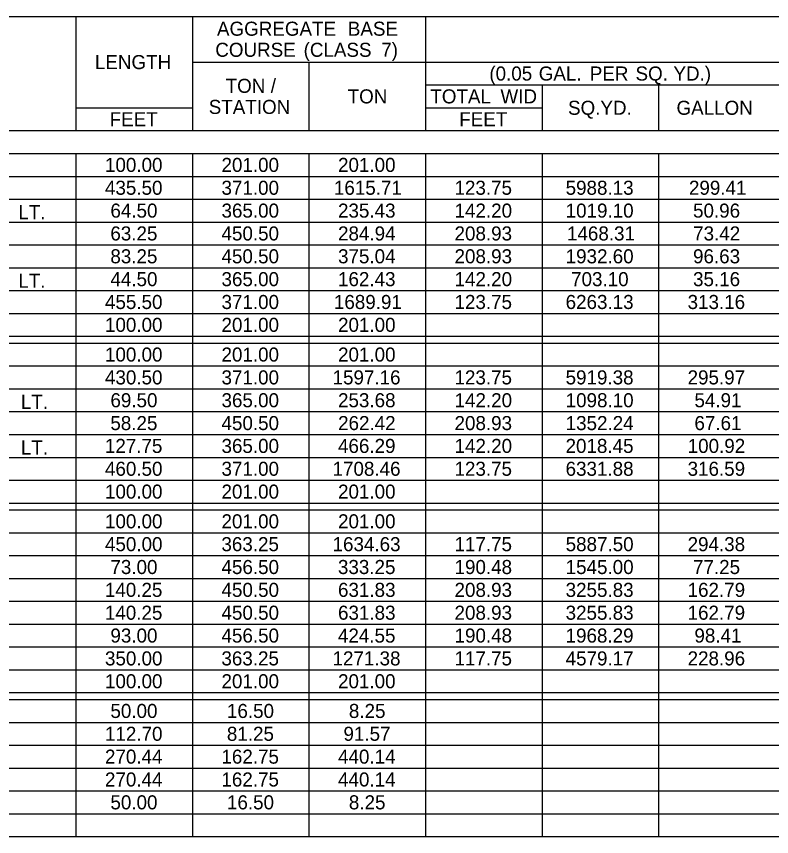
# Model space of a CAD drawing. Extents: x 977434 to 989596, y 1525697 to 1528336.
# Drawn here: x 982968.2 to 983226, y 1527821 to 1528101.1 of the extents above; entities that cross this region are included whole.
import ezdxf

# ---------------------------------------------------------------- set-up
doc = ezdxf.new("R2010")
doc.units = 0
doc.layers.add('Default', color=7, linetype='Continuous')

msp = doc.modelspace()

# ---------------------------------------------------------------- linework, layer by layer
at = {"layer": 'Default'}
for p, q in [((982704.74, 1528101.06), (984062.72, 1528101.06)), ((982988.66, 1528062.06), (982988.66, 1528101.06)), ((983028.44, 1528062.06), (983028.44, 1528101.06)), ((983108, 1528062.06), (983108, 1528101.06)), ((983028.44, 1528085.46), (984062.72, 1528085.46)), ((983068.22, 1528062.06), (983068.22, 1528085.46)), ((983108, 1528077.66), (983346.68, 1528077.66)), ((983147.78, 1528062.06), (983147.78, 1528077.66)), ((983187.56, 1528062.06), (983187.56, 1528077.66)), ((982988.66, 1528069.86), (983028.44, 1528069.86)), ((983028.44, 1528062.06), (983028.44, 1528069.86)), ((983108, 1528069.86), (983147.78, 1528069.86)), ((983147.78, 1528062.06), (983147.78, 1528069.86)), ((982704.74, 1528062.06), (984062.72, 1528062.06)), ((983028.44, 1528062.06), (983147.78, 1528062.06)), ((983147.78, 1528062.06), (983267.12, 1528062.06)), ((982704.74, 1528054.26), (984062.72, 1528054.26)), ((982988.66, 1527821.04), (982988.66, 1528054.26)), ((982988.66, 1527821.04), (982988.66, 1528054.26)), ((983028.44, 1527821.04), (983028.44, 1528054.26)), ((983028.44, 1527821.04), (983028.44, 1528054.26)), ((983068.22, 1527821.04), (983068.22, 1528054.26)), ((983068.22, 1527821.04), (983068.22, 1528054.26)), ((983108, 1527821.04), (983108, 1528054.26)), ((983108, 1527821.04), (983108, 1528054.26)), ((983147.78, 1527821.04), (983147.78, 1528054.26)), ((983147.78, 1527821.04), (983147.78, 1528054.26)), ((983187.56, 1527821.04), (983187.56, 1528054.26)), ((983187.56, 1527821.04), (983187.56, 1528054.26)), ((982704.74, 1528046.46), (984062.72, 1528046.46)), ((982704.74, 1528038.66), (984062.72, 1528038.66)), ((982704.74, 1528030.86), (984062.72, 1528030.86)), ((982704.74, 1528023.06), (984062.72, 1528023.06)), ((982704.74, 1528015.26), (984062.72, 1528015.26)), ((982704.74, 1528007.46), (984062.72, 1528007.46)), ((982704.74, 1527999.66), (984062.72, 1527999.66)), ((982704.74, 1527991.86), (984062.72, 1527991.86)), ((982704.74, 1527989.52), (984062.72, 1527989.52)), ((982704.74, 1527981.72), (984062.72, 1527981.72)), ((982704.74, 1527973.92), (984062.72, 1527973.92)), ((982704.74, 1527966.12), (984062.72, 1527966.12)), ((982704.74, 1527958.32), (984062.72, 1527958.32)), ((982704.74, 1527950.52), (984062.72, 1527950.52)), ((982704.74, 1527942.72), (984062.72, 1527942.72)), ((982704.74, 1527934.92), (984062.72, 1527934.92)), ((982704.74, 1527932.58), (984062.72, 1527932.58)), ((982704.74, 1527924.78), (984062.72, 1527924.78)), ((982704.74, 1527916.98), (984062.72, 1527916.98)), ((982704.74, 1527909.18), (984062.72, 1527909.18)), ((982704.74, 1527901.38), (984062.72, 1527901.38)), ((982704.74, 1527893.58), (984062.72, 1527893.58)), ((982704.74, 1527885.78), (984062.72, 1527885.78)), ((982704.74, 1527877.98), (984062.72, 1527877.98)), ((982704.74, 1527870.18), (984062.72, 1527870.18)), ((982704.74, 1527867.84), (984062.72, 1527867.84)), ((982704.74, 1527860.04), (984062.72, 1527860.04)), ((982704.74, 1527852.24), (984062.72, 1527852.24)), ((982704.74, 1527844.44), (984062.72, 1527844.44)), ((982704.74, 1527836.64), (984062.72, 1527836.64)), ((982704.74, 1527828.84), (984062.72, 1527828.84)), ((982704.74, 1527821.04), (983147.78, 1527821.04)), ((982704.74, 1527821.04), (984062.72, 1527821.04)), ((983147.78, 1527821.04), (983227.34, 1527821.04))]:
    msp.add_line(p, q, dxfattribs=at)

# ---------------------------------------------------------------- texts
for s, p in [('AGGREGATE', (983036.69, 1528094.46)), (' BASE', (983079.58, 1528094.46)), ('COURSE', (983036.12, 1528087.26)), (' (CLASS', (983064.48, 1528087.26)), (' 7)', (983090.98, 1528087.26)), ('LENGTH', (982995.02, 1528083.06)), ('(0.05', (983129.67, 1528079.16)), (' GAL.', (983144.75, 1528079.16)), (' PER', (983162.17, 1528079.16)), (' SQ.', (983177.79, 1528079.16)), (' YD.)', (983190.74, 1528079.16)), ('TON', (983039.65, 1528074.96)), (' /', (983053.27, 1528074.96)), ('TON', (983081.3, 1528071.36)), ('TOTAL', (983109.53, 1528071.36)), (' WID', (983131.68, 1528071.36)), ('STATION', (983033.88, 1528067.76)), ('SQ.YD.', (983156.53, 1528067.46)), ('GALLON', (983193.56, 1528067.46)), ('FEET', (983000.05, 1528063.56)), ('FEET', (983119.39, 1528063.56)), ('100.00', (982998.46, 1528047.96)), ('201.00', (983038.24, 1528047.96)), ('201.00', (983078.02, 1528047.96)), ('435.50', (982998.46, 1528040.16)), ('371.00', (983038.24, 1528040.16)), ('1615.71', (983076.61, 1528040.16)), ('123.75', (983117.77, 1528040.16)), ('5988.13', (983155.71, 1528040.16)), ('299.41', (983197.81, 1528040.16)), (' LT.', (982967.1, 1528031.82)), ('64.50', (983000.32, 1528032.36)), ('365.00', (983038.24, 1528032.36)), ('235.43', (983078.01, 1528032.36)), ('142.20', (983117.8, 1528032.36)), ('1019.10', (983155.72, 1528032.36)), ('50.96', (983199.21, 1528032.36)), ('63.25', (983000.3, 1528024.56)), ('450.50', (983038.24, 1528024.56)), ('284.94', (983078.02, 1528024.56)), ('208.93', (983117.79, 1528024.56)), ('1468.31', (983156.17, 1528024.56)), ('73.42', (983199.24, 1528024.56)), ('83.25', (983000.3, 1528016.76)), ('450.50', (983038.24, 1528016.76)), ('375.04', (983078.02, 1528016.76)), ('208.93', (983117.79, 1528016.76)), ('1932.60', (983155.72, 1528016.76)), ('96.63', (983199.21, 1528016.76)), (' LT.', (982967.1, 1528008.42)), ('44.50', (983000.32, 1528008.96)), ('365.00', (983038.24, 1528008.96)), ('162.43', (983078.01, 1528008.96)), ('142.20', (983117.8, 1528008.96)), ('703.10', (983157.58, 1528008.96)), ('35.16', (983199.21, 1528008.96)), ('455.50', (982998.46, 1528001.16)), ('371.00', (983038.24, 1528001.16)), ('1689.91', (983076.61, 1528001.16)), ('123.75', (983117.77, 1528001.16)), ('6263.13', (983155.71, 1528001.16)), ('313.16', (983197.35, 1528001.16)), ('100.00', (982998.46, 1527993.36)), ('201.00', (983038.24, 1527993.36)), ('201.00', (983078.02, 1527993.36)), ('100.00', (982998.46, 1527983.22)), ('201.00', (983038.24, 1527983.22)), ('201.00', (983078.02, 1527983.22)), ('430.50', (982998.46, 1527975.42)), ('371.00', (983038.24, 1527975.42)), ('1597.16', (983076.15, 1527975.42)), ('123.75', (983117.77, 1527975.42)), ('5919.38', (983155.7, 1527975.42)), ('295.97', (983197.35, 1527975.42)), (' LT.', (982967.97, 1527967.08)), ('69.50', (983000.32, 1527967.62)), ('365.00', (983038.24, 1527967.62)), ('253.68', (983078.01, 1527967.62)), ('142.20', (983117.8, 1527967.62)), ('1098.10', (983155.72, 1527967.62)), ('54.91', (983199.68, 1527967.62)), ('58.25', (983000.3, 1527959.82)), ('450.50', (983038.24, 1527959.82)), ('262.42', (983078.04, 1527959.82)), ('208.93', (983117.79, 1527959.82)), ('1352.24', (983155.72, 1527959.82)), ('67.61', (983199.68, 1527959.82)), (' LT.', (982967.97, 1527951.48)), ('127.75', (982998.43, 1527952.02)), ('365.00', (983038.24, 1527952.02)), ('466.29', (983078.01, 1527952.02)), ('142.20', (983117.8, 1527952.02)), ('2018.45', (983155.69, 1527952.02)), ('100.92', (983197.38, 1527952.02)), ('460.50', (982998.46, 1527944.22)), ('371.00', (983038.24, 1527944.22)), ('1708.46', (983076.15, 1527944.22)), ('123.75', (983117.77, 1527944.22)), ('6331.88', (983155.7, 1527944.22)), ('316.59', (983197.35, 1527944.22)), ('100.00', (982998.46, 1527936.42)), ('201.00', (983038.24, 1527936.42)), ('201.00', (983078.02, 1527936.42)), ('100.00', (982998.46, 1527926.28)), ('201.00', (983038.24, 1527926.28)), ('201.00', (983078.02, 1527926.28)), ('450.00', (982998.46, 1527918.48)), ('363.25', (983038.21, 1527918.48)), ('1634.63', (983076.15, 1527918.48)), ('117.75', (983117.77, 1527918.48)), ('5887.50', (983155.72, 1527918.48)), ('294.38', (983197.35, 1527918.48)), ('73.00', (983000.32, 1527910.68)), ('456.50', (983038.24, 1527910.68)), ('333.25', (983077.99, 1527910.68)), ('190.48', (983117.79, 1527910.68)), ('1545.00', (983155.72, 1527910.68)), ('77.25', (983199.2, 1527910.68)), ('140.25', (982998.43, 1527902.88)), ('450.50', (983038.24, 1527902.88)), ('631.83', (983078.01, 1527902.88)), ('208.93', (983117.79, 1527902.88)), ('3255.83', (983155.71, 1527902.88)), ('162.79', (983197.35, 1527902.88)), ('140.25', (982998.43, 1527895.08)), ('450.50', (983038.24, 1527895.08)), ('631.83', (983078.01, 1527895.08)), ('208.93', (983117.79, 1527895.08)), ('3255.83', (983155.71, 1527895.08)), ('162.79', (983197.35, 1527895.08)), ('93.00', (983000.32, 1527887.28)), ('456.50', (983038.24, 1527887.28)), ('424.55', (983077.99, 1527887.28)), ('190.48', (983117.79, 1527887.28)), ('1968.29', (983155.7, 1527887.28)), ('98.41', (983199.68, 1527887.28)), ('350.00', (982998.46, 1527879.48)), ('363.25', (983038.21, 1527879.48)), ('1271.38', (983076.14, 1527879.48)), ('4579.17', (983155.71, 1527879.48)), ('228.96', (983197.35, 1527879.48)), ('117.75', (983117.77, 1527879.48)), ('100.00', (982998.46, 1527871.68)), ('201.00', (983038.24, 1527871.68)), ('201.00', (983078.02, 1527871.68)), ('50.00', (983000.32, 1527861.54)), ('16.50', (983040.1, 1527861.54)), ('8.25', (983081.72, 1527861.54)), ('112.70', (982998.46, 1527853.74)), ('81.25', (983040.08, 1527853.74)), ('91.57', (983079.87, 1527853.74)), ('270.44', (982998.46, 1527845.94)), ('162.75', (983038.21, 1527845.94)), ('440.14', (983078.02, 1527845.94)), ('270.44', (982998.46, 1527838.14)), ('162.75', (983038.21, 1527838.14)), ('440.14', (983078.02, 1527838.14)), ('50.00', (983000.32, 1527830.34)), ('16.50', (983040.1, 1527830.34)), ('8.25', (983081.72, 1527830.34))]:
    msp.add_text(s, height=4.8, dxfattribs=at).set_placement(p)

doc.saveas('drawing.dxf')
